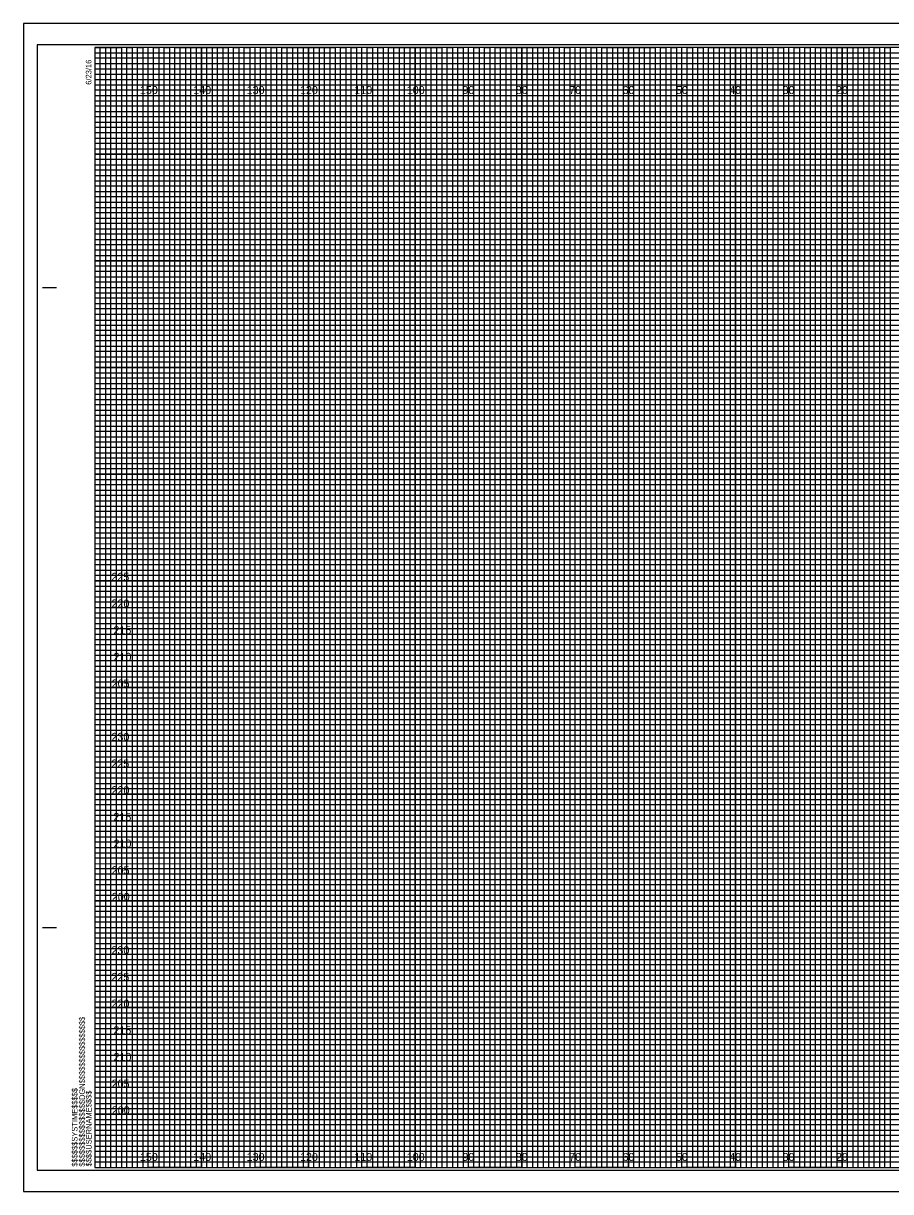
# Model space of a CAD drawing. Extents: x -13 to 323, y -5 to 654.
# Drawn here: x -13.4 to 149.1, y 435.5 to 654.5 of the extents above; entities that cross this region are included whole.
import ezdxf

# ---------------------------------------------------------------- set-up
doc = ezdxf.new("R2010")
doc.units = 0
for name, color, linetype in [('Prop XS Elevation Labels', 7, 'Continuous'), ('Prop XS Offset Labels', 7, 'Continuous'), ('Sheet Cross Section CELL', 7, 'Continuous'), ('Sheet Cross Section Grid Major CELL', 7, 'Continuous'), ('Sheet Cross Section Grid Middle CELL', 7, 'Continuous'), ('Sheet Cross Section Grid Minor 1 CELL', 7, 'Continuous'), ('Sheet Cross Section Grid Minor 2 CELL', 7, 'Continuous'), ('Sheet Cutting Line CELL', 7, 'Continuous'), ('Sheet DOT Grid CELL', 7, 'Continuous'), ('Sheet Plot Border Inside CELL', 7, 'Continuous'), ('Sheet Plot Border Outside CELL', 7, 'Continuous')]:
    doc.layers.add(name, color=color, linetype=linetype)

msp = doc.modelspace()

# ---------------------------------------------------------------- linework, layer by layer
at = {"layer": 'Sheet Cross Section CELL'}
for p, q in [((-9.8, 605), (-7.3, 605)), ((-9.7, 605), (-7.2, 605)), ((-9.8, 485), (-7.3, 485)), ((-9.7, 485), (-7.2, 485)), ((0, 440), (0, 440)), ((0, 440), (0, 440)), ((0, 440), (0, 440)), ((0, 440), (0, 440)), ((0, 440), (0, 440)), ((0, 440), (0, 440)), ((0, 440), (0, 440))]:
    msp.add_line(p, q, dxfattribs=at)
msp.add_lwpolyline([(320, 650), (0, 650), (0, 440), (320, 440)], close=True, dxfattribs=at)
at = {"layer": 'Sheet Cross Section Grid Major CELL'}
for p, q in [((10, 650), (0, 650)), ((10, 440), (10, 650)), ((30, 650), (20, 650)), ((20, 650), (20, 440)), ((30, 440), (30, 650)), ((50, 650), (40, 650)), ((40, 650), (40, 440)), ((50, 440), (50, 650)), ((70, 650), (60, 650)), ((60, 650), (60, 440)), ((70, 440), (70, 650)), ((90, 650), (80, 650)), ((80, 650), (80, 440)), ((90, 440), (90, 650)), ((110, 650), (100, 650)), ((100, 650), (100, 440)), ((110, 440), (110, 650)), ((130, 650), (120, 650)), ((120, 650), (120, 440)), ((130, 440), (130, 650)), ((150, 650), (140, 650)), ((140, 650), (140, 440)), ((20, 440), (10, 440)), ((40, 440), (30, 440)), ((60, 440), (50, 440)), ((80, 440), (70, 440)), ((100, 440), (90, 440)), ((120, 440), (110, 440)), ((140, 440), (130, 440))]:
    msp.add_line(p, q, dxfattribs=at)
for points in [[(0, 640), (320, 640), (320, 630), (0, 630)], [(0, 620), (320, 620), (320, 610), (0, 610)], [(0, 600), (320, 600), (320, 590), (0, 590)], [(0, 580), (320, 580), (320, 570), (0, 570)], [(0, 560), (320, 560), (320, 550), (0, 550)], [(0, 540), (320, 540), (320, 530), (0, 530)], [(0, 520), (320, 520), (320, 510), (0, 510)], [(0, 500), (320, 500), (320, 490), (0, 490)], [(0, 480), (320, 480), (320, 470), (0, 470)], [(0, 460), (320, 460), (320, 450), (0, 450)]]:
    msp.add_lwpolyline(points, dxfattribs=at)
at = {"layer": 'Sheet Cross Section Grid Middle CELL'}
for points in [[(0, 650), (5, 650), (5, 440), (15, 440), (15, 650), (25, 650), (25, 440), (35, 440), (35, 650), (45, 650), (45, 440), (55, 440), (55, 650), (65, 650), (65, 440), (75, 440), (75, 650), (85, 650), (85, 440), (95, 440), (95, 650), (105, 650), (105, 440), (115, 440), (115, 650), (125, 650), (125, 440), (135, 440), (135, 650), (145, 650), (145, 440), (155, 440)], [(0, 645), (275, 645)], [(0, 625), (320, 625), (320, 635), (0, 635)], [(0, 605), (320, 605), (320, 615), (0, 615)], [(0, 585), (320, 585), (320, 595), (0, 595)], [(0, 565), (320, 565), (320, 575), (0, 575)], [(0, 545), (320, 545), (320, 555), (0, 555)], [(0, 525), (320, 525), (320, 535), (0, 535)], [(0, 505), (320, 505), (320, 515), (0, 515)], [(0, 485), (320, 485), (320, 495), (0, 495)], [(0, 465), (320, 465), (320, 475), (0, 475)], [(0, 445), (320, 445), (320, 455), (0, 455)]]:
    msp.add_lwpolyline(points, dxfattribs=at)
at = {"layer": 'Sheet Cross Section Grid Minor 1 CELL'}
for p, q in [((0, 649), (260, 649)), ((260, 647.98), (0, 647.98)), ((0, 647.98), (0, 647)), ((0, 647), (260, 647)), ((260, 645.89), (0, 645.89)), ((0, 645.89), (0, 644)), ((0, 644), (320, 644))]:
    msp.add_line(p, q, dxfattribs=at)
for points in [[(0, 643), (270, 643), (320, 643), (320, 642), (0, 642)], [(0, 641), (320, 641), (320, 639), (0, 639)], [(0, 638), (320, 638), (320, 637), (0, 636.98)], [(0, 636), (320, 636), (320, 634), (0, 634)], [(0, 633), (320, 633), (320, 632), (0, 632)], [(0, 631), (320, 631), (320, 629), (0, 629)], [(0, 628), (320, 628), (320, 627), (0, 627)], [(0, 626), (320, 626), (320, 624), (0, 624)], [(0, 623), (320, 623), (320, 622), (0, 622)], [(0, 621), (320, 621), (320, 619), (0, 619)], [(0, 618), (320, 618), (320, 617), (0, 617)], [(0, 616), (320, 616), (320, 613.95), (320, 613), (320, 612), (0, 612)], [(0, 614), (320, 614), (320, 613), (0, 613)], [(0, 611), (320, 611), (320, 609), (0, 609.03)], [(0, 609.03), (320, 609), (320, 608), (0, 608)], [(0, 607), (320, 607), (320, 606), (0, 606)], [(0, 604), (320, 604), (320, 603), (0, 603)], [(0, 602), (320, 602), (320, 601), (0, 601)], [(-0.07, 598.89), (320, 598.89), (320, 597.88), (-0.07, 597.88)], [(0, 597), (320, 597), (320, 596), (0, 596)], [(0, 594), (320, 594), (320, 593), (0, 593)], [(0, 592), (320, 592), (320, 591), (0, 591)], [(0, 589), (320, 589), (320, 588), (0, 588)], [(0, 587), (320, 587), (320, 586), (0, 586)], [(0, 584), (320, 584), (320, 583), (0, 583)], [(0, 582), (320, 582), (320, 581), (0, 581)], [(0, 579), (320, 579), (319.99, 577.98), (0, 578)], [(0, 577), (320, 577), (320, 576), (0, 576)], [(0, 574), (320, 574), (320, 573), (0, 573)], [(0, 572), (320, 572), (320, 571), (0, 571)], [(0, 569), (320, 569), (320, 568), (0, 568)], [(0, 567), (320, 567), (320, 566), (0, 566)], [(0, 564), (320, 564), (320, 563), (0, 563)], [(0, 562), (320, 562), (320, 561), (0, 561)], [(0, 559), (320, 559), (320, 558), (0, 558)], [(0, 556.99), (320.07, 556.91), (320, 556), (0, 556)], [(0, 554), (320, 554), (320, 553), (0, 553)], [(0, 552), (320, 552), (320, 551), (0, 551)], [(0, 549), (320, 549), (320, 548), (0, 548)], [(0, 547), (320, 547), (320, 546), (0, 546)], [(0, 544), (320, 544), (320, 543), (0, 543)], [(0, 542), (320, 542), (320, 541), (0, 541)], [(0, 539), (320, 539), (320, 538), (0, 538)], [(0, 537), (320, 537), (320, 536), (0, 536)], [(0, 534), (320, 534), (320, 533), (0, 533)], [(0, 532), (320, 532), (320, 531), (0, 531)], [(0, 529), (320, 529), (320, 528), (0, 528)], [(0, 527), (320, 527), (320, 526), (0, 526)], [(0, 524), (320, 524), (320, 523), (0, 523)], [(0, 522), (320, 522), (320, 521), (0, 521)], [(0, 519), (320, 519), (319.99, 517.98), (0, 518)], [(0, 517), (320, 517), (320, 516), (0, 516)], [(0, 514), (320, 514), (320, 513), (0, 513)], [(0, 512), (320, 512), (320, 511), (0, 511)], [(0, 509), (320, 509), (320, 508), (0, 508)], [(0, 507), (320, 507), (320, 506), (0, 506)], [(0, 504), (320, 504), (320, 503), (0, 503)], [(0, 502), (320, 502), (320, 501), (0, 501)], [(0, 499), (320, 499), (320, 498), (0, 498)], [(0, 496.99), (320.07, 496.91), (320, 496), (0, 496)], [(0, 494), (320, 494), (320, 493), (0, 493)], [(0, 492), (320, 492), (320, 491), (0, 491)], [(0, 489), (320, 489), (320, 488), (0, 488)], [(0, 487), (320, 487), (320, 486), (0, 486)], [(0, 484), (320, 484), (320, 483), (0, 483)], [(0, 482), (320, 482), (320, 481), (0, 481)], [(0, 479), (320, 479), (320, 478), (0, 478)], [(0, 477), (320, 477), (320, 476), (0, 476)], [(0, 474), (320, 474), (320, 473), (0, 473)], [(0, 472), (320, 472), (320, 471), (0, 471)], [(0, 469), (320, 469), (320, 468), (0, 468)], [(0, 467), (320, 467), (320, 466), (0, 466)], [(0, 464), (320, 464), (320, 463), (0, 463)], [(0, 462), (320, 462), (320, 461), (0, 461)], [(0, 459), (320, 459), (320, 458), (0, 458)], [(0, 457), (320, 457), (320, 456), (0, 456)], [(0, 454), (320, 454), (320, 453), (0, 453)], [(0, 452), (320, 452), (320, 451), (0, 451)], [(0, 449), (320, 449), (320, 448), (0, 448)], [(0, 447), (320, 447), (320, 446), (0, 446)], [(0, 444), (320, 444), (320, 443), (0, 443)], [(0, 442), (320, 442), (320, 441), (0, 441)]]:
    msp.add_lwpolyline(points, dxfattribs=at)
at = {"layer": 'Sheet Cross Section Grid Minor 2 CELL'}
for points in [[(0, 440), (1, 440), (1, 650), (2, 650), (2, 440)], [(2, 440), (3, 440), (3, 650), (4, 650), (4, 440)], [(5, 440), (6, 440), (6, 650), (7, 650), (7, 440)], [(7, 440), (8, 440), (8, 650), (9, 650), (9, 440)], [(10, 440), (11, 440), (11, 650), (12, 650), (12, 440)], [(12, 440), (13, 440), (13, 650), (14, 650), (14, 440)], [(15, 440), (16, 440), (16, 650), (17, 650), (17, 440)], [(17, 440), (18, 440), (18, 650), (19, 650), (19, 440)], [(20, 440), (21, 440), (21, 650), (22, 650), (22, 440)], [(22, 440), (23, 440), (23, 650), (24, 650), (24, 440)], [(25, 440), (26, 440), (26, 650), (27, 650), (27, 440)], [(27, 440), (28, 440), (28, 650), (29, 650), (29, 440)], [(30, 440), (31, 440), (31, 650), (32, 650), (32, 440)], [(32, 440), (33, 440), (33, 650), (34, 650), (34, 440)], [(35, 440), (36, 440), (36, 650), (37, 650), (37, 440)], [(37, 440), (38, 440), (38, 650), (39, 650), (39, 440)], [(40, 440), (41, 440), (41, 650), (42, 650), (42, 440)], [(42, 440), (43, 440), (43, 650), (44, 650), (44, 440)], [(45, 440), (46, 440), (46, 650), (47, 650), (47, 440)], [(47, 440), (48, 440), (48, 650), (49, 650), (49, 440)], [(50, 440), (51, 440), (51, 650), (52, 650), (52, 440)], [(52, 440), (53, 440), (53, 650), (54, 650), (54, 440)], [(55, 440), (56, 440), (56, 650), (57, 650), (57, 440)], [(57, 440), (58, 440), (58, 650), (59, 650), (59, 440)], [(60, 440), (61, 440), (61, 650), (62, 650), (62, 440)], [(62, 440), (63, 440), (63, 650), (64, 650), (64, 440)], [(65, 440), (66, 440), (66, 650), (67, 650), (67, 440)], [(67, 440), (68, 440), (68, 650), (69, 650), (69, 440)], [(70, 440), (71, 440), (71, 650), (72, 650), (72, 440)], [(72, 440), (73, 440), (73, 650), (74, 650), (74, 440)], [(75, 440), (76, 440), (76, 650), (77, 650), (77, 440)], [(77, 440), (78, 440), (78, 650), (79, 650), (79, 440)], [(80, 440), (81, 440), (81, 650), (82, 650), (82, 440)], [(82, 440), (83, 440), (83, 650), (84, 650), (84, 440)], [(85, 440), (86, 440), (86, 650), (87, 650), (87, 440)], [(87, 440), (88, 440), (88, 650), (89, 650), (89, 440)], [(90, 440), (91, 440), (91, 650), (92, 650), (92, 440)], [(92, 440), (93, 440), (93, 650), (94, 650), (94, 440)], [(95, 440), (96, 440), (96, 650), (97, 650), (97, 440)], [(97, 440), (98, 440), (98, 650), (99, 650), (99, 440)], [(100, 440), (101, 440), (101, 650), (102, 650), (102, 440)], [(102, 440), (103, 440), (103, 650), (104, 650), (104, 440)], [(105, 440), (106, 440), (106, 650), (107, 650), (107, 440)], [(107, 440), (108, 440), (108, 650), (109, 650), (109, 440)], [(110, 440), (111, 440), (111, 650), (112, 650), (112, 440)], [(112, 440), (113, 440), (113, 650), (114, 650), (114, 440)], [(115, 440), (116, 440), (116, 650), (117, 650), (117, 440)], [(117, 440), (118, 440), (118, 650), (119, 650), (119, 440)], [(120, 440), (121, 440), (121, 650), (122, 650), (122, 440)], [(122, 440), (123, 440), (123, 650), (124, 650), (124, 440)], [(125, 440), (126, 440), (126, 650), (127, 650), (127, 440)], [(127, 440), (128, 440), (128, 650), (129, 650), (129, 440)], [(130, 440), (131, 440), (131, 650), (132, 650), (132, 440)], [(132, 440), (133, 440), (133, 650), (134, 650), (134, 440)], [(135, 440), (136, 440), (136, 650), (137, 650), (137, 440)], [(137, 440), (138, 440), (138, 650), (139, 650), (139, 440)], [(140, 440), (141, 440), (141, 650), (142, 650), (142, 440)], [(142, 440), (143, 440), (143, 650), (144, 650), (144, 440)], [(145, 440), (146, 440), (146, 650), (147, 650), (147, 440)], [(147, 440), (148, 440), (148, 650), (149, 650), (149, 440)]]:
    msp.add_lwpolyline(points, dxfattribs=at)
at = {"layer": 'Sheet Cutting Line CELL'}
for p, q in [((323.3, 654.5), (-13.4, 654.5)), ((-13.4, 654.5), (-13.4, 435.5)), ((-13.4, 435.5), (323.3, 435.5))]:
    msp.add_line(p, q, dxfattribs=at)
at = {"layer": 'Sheet DOT Grid CELL'}
for p, q in [((10, 440), (10, 650)), ((20, 440), (20, 650)), ((30, 440), (30, 650)), ((40, 440), (40, 650)), ((50, 440), (50, 650)), ((60, 440), (60, 650)), ((70, 440), (70, 650)), ((80, 440), (80, 650)), ((90, 440), (90, 650)), ((100, 440), (100, 650)), ((110, 440), (110, 650)), ((120, 440), (120, 650)), ((130, 440), (130, 650)), ((140, 440), (140, 650)), ((0, 640), (320, 640)), ((0, 630), (320, 630)), ((0, 620), (320, 620)), ((0, 610), (320, 610)), ((0, 600), (320, 600)), ((0, 590), (320, 590)), ((0, 580), (320, 580)), ((0, 570), (320, 570)), ((0, 560), (320, 560)), ((0, 550), (320, 550)), ((0, 540), (320, 540)), ((0, 530), (320, 530)), ((0, 520), (320, 520)), ((0, 510), (320, 510)), ((0, 500), (320, 500)), ((0, 490), (320, 490)), ((0, 480), (320, 480)), ((0, 470), (320, 470)), ((0, 460), (320, 460)), ((0, 450), (320, 450))]:
    msp.add_line(p, q, dxfattribs=at)
at = {"layer": 'Sheet Plot Border Inside CELL'}
msp.add_lwpolyline([(-10.8, 439.5), (322.4, 439.5), (322.4, 650.5), (-10.8, 650.5)], close=True, dxfattribs=at)
at = {"layer": 'Sheet Plot Border Outside CELL'}
msp.add_lwpolyline([(-13.4, 435.5), (323.3, 435.5), (323.3, 654.5), (-13.4, 654.5)], close=True, dxfattribs=at)

# ---------------------------------------------------------------- texts
at = {"layer": 'Prop XS Elevation Labels'}
for s, p in [('225', (3.1, 550)), ('220', (3.12, 545)), ('215', (3.48, 540)), ('210', (3.5, 535)), ('205', (3.15, 530)), ('230', (3.11, 520)), ('225', (3.1, 515)), ('220', (3.12, 510)), ('215', (3.48, 505)), ('210', (3.5, 500)), ('205', (3.15, 495)), ('200', (3.17, 490)), ('230', (3.11, 480)), ('225', (3.1, 475)), ('220', (3.12, 470)), ('215', (3.48, 465)), ('210', (3.5, 460)), ('205', (3.15, 455)), ('200', (3.17, 450))]:
    msp.add_text(s, height=1.5, dxfattribs=at).set_placement(p)
at = {"layer": 'Prop XS Offset Labels'}
for s, p in [('150', (8.44, 641.25)), ('140', (18.44, 641.25)), ('130', (28.44, 641.25)), ('120', (38.44, 641.25)), ('110', (48.62, 641.25)), ('100', (58.44, 641.25)), ('90', (68.86, 641.25)), ('80', (78.86, 641.25)), ('70', (88.86, 641.25)), ('60', (98.86, 641.25)), ('50', (108.86, 641.25)), ('40', (118.86, 641.25)), ('30', (128.86, 641.25)), ('20', (138.86, 641.25)), ('150', (8.44, 441.25)), ('140', (18.44, 441.25)), ('130', (28.44, 441.25)), ('120', (38.44, 441.25)), ('110', (48.62, 441.25)), ('100', (58.44, 441.25)), ('90', (68.86, 441.25)), ('80', (78.86, 441.25)), ('70', (88.86, 441.25)), ('60', (98.86, 441.25)), ('50', (108.86, 441.25)), ('40', (118.86, 441.25)), ('30', (128.86, 441.25)), ('20', (138.86, 441.25))]:
    msp.add_text(s, height=1.5, dxfattribs=at).set_placement(p)
at = {"layer": 'Sheet Cross Section CELL'}
for s, p in [('6/23/16', (-0.65, 643)), ('$$$$$$$$$$$$$$$$DGN$$$$$$$$$$$$$$$$', (-1.88, 440.18)), ('$$$$$$SYSTIME$$$$$', (-3.26, 440.18)), ('$$$$USERNAME$$$$', (-0.62, 440.23))]:
    msp.add_text(s, height=1.05, rotation=90, dxfattribs=at).set_placement(p)

doc.saveas('drawing.dxf')
